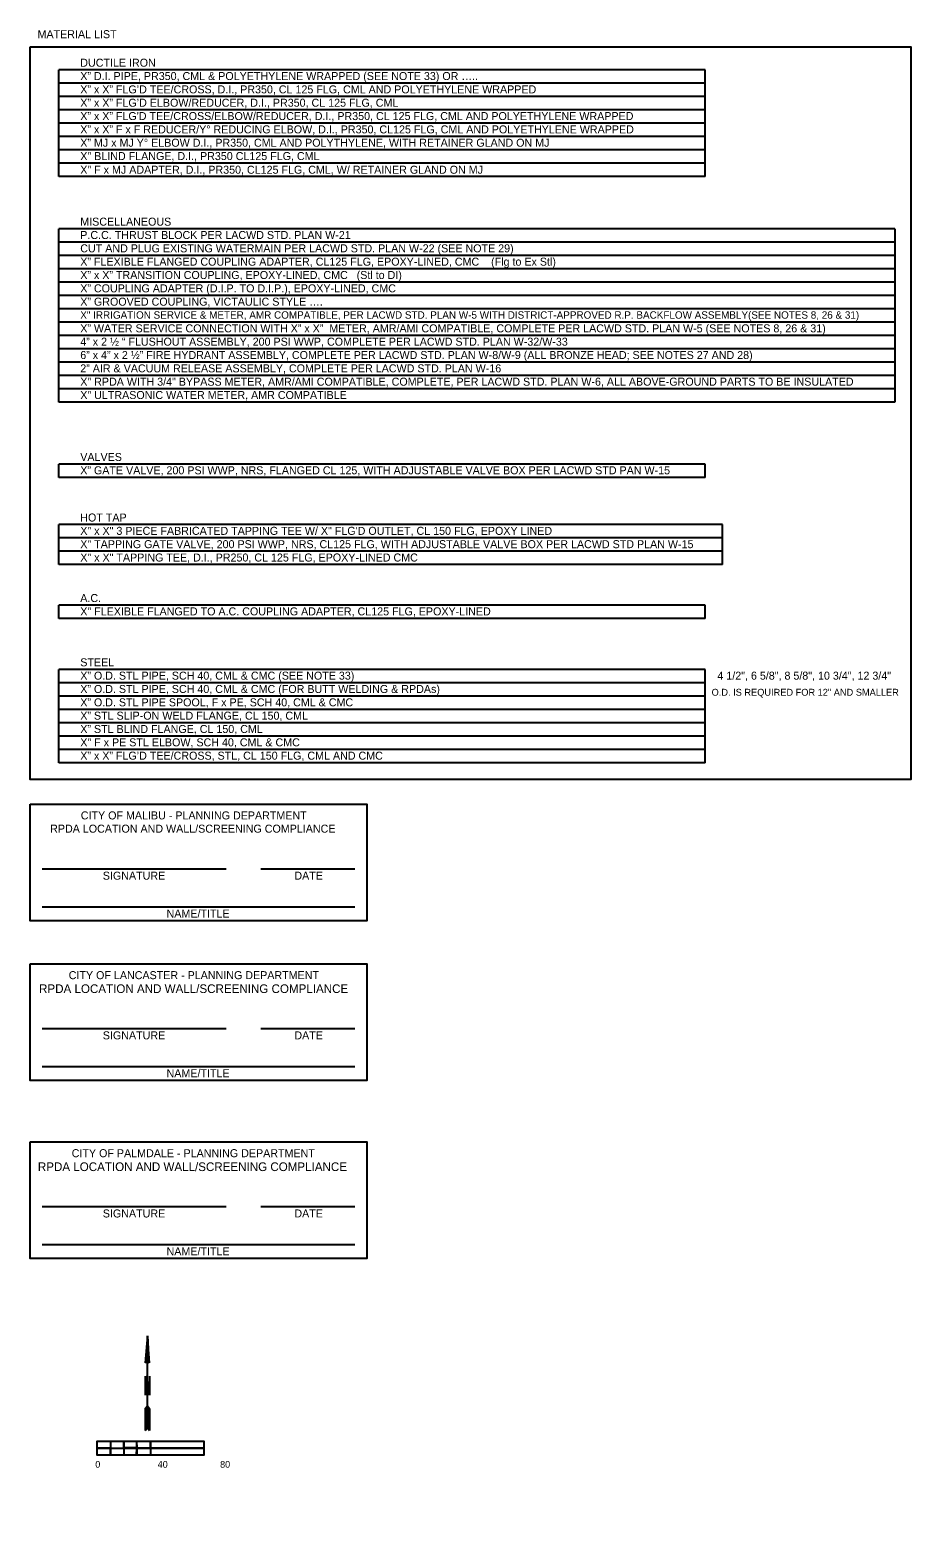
# Model space of a CAD drawing. Extents: x 837 to 1117, y 1316 to 1424.
# Drawn here: x 880.54 to 893.75, y 1401.27 to 1423.81 of the extents above; entities that cross this region are included whole.
import ezdxf

# ---------------------------------------------------------------- set-up
doc = ezdxf.new("R2010")
doc.units = 0
for name, color, linetype in [('BASEMAP', 7, 'Continuous'), ('LLINES', 7, 'Continuous'), ('TEXT', 7, 'Continuous')]:
    doc.layers.add(name, color=color, linetype=linetype)

# ---------------------------------------------------------------- blocks, each defined once
blk = doc.blocks.new('_U0')
at = {"layer": 'LLINES'}
for p, q in [((0, 1378), (-79, 591)), ((0, 1378), (-64, 606)), ((0, 1378), (-49, 620)), ((0, 1378), (-35, 634)), ((0, 1378), (-22, 647)), ((0, 1378), (-9, 660)), ((79, 591), (0, 1378)), ((0, 1378), (4, 666)), ((0, 1378), (43, 626)), ((0, 1378), (57, 612)), ((0, 1378), (29, 640)), ((2, 1302), (16, 653)), ((-79, 591), (0, 669)), ((0, 39), (0, 669)), ((0, 669), (79, 591)), ((16, 654), (29, 642)), ((-79, 197), (79, -118)), ((-79, 197), (-79, -354)), ((-79, 189), (79, -126)), ((-79, 181), (79, -134)), ((-79, 173), (79, -142)), ((-79, 165), (79, -150)), ((-79, 157), (79, -157)), ((-79, 150), (79, -165)), ((-79, 142), (79, -173)), ((-79, 134), (79, -181)), ((-79, 126), (79, -189)), ((-79, 118), (79, -197)), ((-79, 110), (79, -205)), ((-79, 102), (79, -213)), ((-79, 94), (79, -220)), ((-79, 87), (79, -228)), ((-79, 79), (79, -236)), ((-79, 71), (79, -244)), ((-79, 63), (79, -252)), ((-79, 55), (79, -260)), ((-79, 47), (79, -268)), ((-79, 39), (79, -276)), ((-79, 31), (79, -283)), ((-79, 24), (79, -291)), ((-79, 16), (79, -299)), ((-79, 8), (79, -307)), ((79, 197), (79, -354)), ((-79, 0), (79, -315)), ((-79, -8), (79, -323)), ((-79, -16), (79, -331)), ((-79, -24), (79, -339)), ((-79, -31), (79, -346)), ((-79, -39), (79, -354)), ((-79, -39), (79, -354)), ((0, -669), (0, -197)), ((0, -669), (-79, -748)), ((0, -669), (-79, -748)), ((0, -669), (-79, -748)), ((-79, -748), (-79, -1378)), ((-79, -748), (-79, -1378)), ((-79, -748), (-79, -1378)), ((-71, -748), (-71, -740)), ((-71, -748), (-71, -1370)), ((-63, -748), (-63, -732)), ((-63, -748), (-63, -1362)), ((-55, -748), (-55, -724)), ((-55, -748), (-55, -1354)), ((-47, -748), (-47, -717)), ((-47, -748), (-47, -1346)), ((-39, -748), (-39, -709)), ((-39, -748), (-39, -1339)), ((-31, -748), (-31, -701)), ((-31, -748), (-31, -1331)), ((-24, -748), (-24, -693)), ((-24, -748), (-24, -1323)), ((-16, -748), (-16, -685)), ((-16, -748), (-16, -1315)), ((-8, -748), (-8, -677)), ((-8, -748), (-8, -1307)), ((-8, -748), (-8, -1307)), ((0, -748), (0, -631)), ((79, -748), (0, -669)), ((0, -748), (0, -1299)), ((8, -748), (8, -677)), ((8, -748), (8, -1307)), ((16, -748), (16, -685)), ((16, -748), (16, -1315)), ((24, -748), (24, -693)), ((24, -748), (24, -1323)), ((31, -748), (31, -701)), ((31, -748), (31, -1331)), ((39, -748), (39, -709)), ((39, -748), (39, -1339)), ((47, -748), (47, -717)), ((47, -748), (47, -1346)), ((55, -748), (55, -724)), ((55, -748), (55, -1354)), ((63, -748), (63, -732)), ((63, -748), (63, -1362)), ((71, -748), (71, -740)), ((71, -748), (71, -1370)), ((79, -1378), (79, -748)), ((79, -748), (79, -1378)), ((-79, -1378), (0, -1299)), ((0, -1299), (79, -1378))]:
    blk.add_line(p, q, dxfattribs=at)
blk = doc.blocks.new('_U8')
at = {"layer": 'LLINES'}
for p, q in [((-2.295, -1.877), (1.489, 2.511)), ((-0.692, 0.559), (-0.114, 0.074)), ((-1.185, -0.013), (-0.626, -0.481)), ((-2.111, -1.086), (-1.533, -1.571))]:
    blk.add_line(p, q, dxfattribs=at)
for points in [[(-2.584, -1.635), (1.2, 2.753), (1.778, 2.268), (-2.006, -2.12)], [(-0.692, 0.559), (1.2, 2.753), (1.489, 2.511), (-0.403, 0.317)], [(-0.915, -0.239), (-0.422, 0.333), (-0.114, 0.074), (-0.607, -0.498)], [(-1.822, -1.329), (-1.349, -0.78), (-1.06, -1.023), (-1.533, -1.571)], [(-1.638, -0.538), (-1.185, -0.013), (-0.903, -0.249), (-1.356, -0.774)], [(-1.822, -1.329), (-2.295, -1.877), (-2.584, -1.635), (-2.111, -1.086)]]:
    blk.add_lwpolyline(points, close=True, dxfattribs=at)
blk.add_lwpolyline([(-2.584, -1.635), (-1.638, -0.538), (-1.06, -1.023)], dxfattribs=at)
blk.add_text('0                       40                     80', height=0.36477, rotation=49.23155, dxfattribs=at).set_placement((-1.549, -2.642))
blk = doc.blocks.new('_U3')
at = {"layer": 'BASEMAP'}
for p, q in [((-2.343, 0.365), (0.416, 0.365)), ((0.936, 0.365), (2.343, 0.365)), ((-2.343, -0.203), (2.343, -0.203))]:
    blk.add_line(p, q, dxfattribs=at)
at = {"layer": 'TEXT'}
for s, p in [('SIGNATURE', (-1.435, 0.203)), ('DATE', (1.438, 0.203)), ('NAME/TITLE', (-0.479, -0.365))]:
    blk.add_text(s, height=0.12, dxfattribs=at).set_placement(p)
blk = doc.blocks.new('_U5')
at = {"layer": 'BASEMAP'}
for p, q in [((-2.343, 0.365), (0.416, 0.365)), ((0.936, 0.365), (2.343, 0.365)), ((-2.343, -0.203), (2.343, -0.203))]:
    blk.add_line(p, q, dxfattribs=at)
at = {"layer": 'TEXT'}
for s, p in [('SIGNATURE', (-1.435, 0.203)), ('DATE', (1.438, 0.203)), ('NAME/TITLE', (-0.479, -0.365))]:
    blk.add_text(s, height=0.12, dxfattribs=at).set_placement(p)
blk = doc.blocks.new('_U7')
at = {"layer": 'BASEMAP'}
for p, q in [((-2.343, 0.365), (0.416, 0.365)), ((0.936, 0.365), (2.343, 0.365)), ((-2.343, -0.203), (2.343, -0.203))]:
    blk.add_line(p, q, dxfattribs=at)
at = {"layer": 'TEXT'}
for s, p in [('SIGNATURE', (-1.435, 0.203)), ('DATE', (1.438, 0.203)), ('NAME/TITLE', (-0.479, -0.365))]:
    blk.add_text(s, height=0.12, dxfattribs=at).set_placement(p)

msp = doc.modelspace()

# ---------------------------------------------------------------- linework, layer by layer
at = {"layer": 'BASEMAP'}
for p, q in [((890.667, 1423.212), (880.972, 1423.212)), ((880.972, 1423.012), (880.972, 1423.212)), ((890.667, 1423.012), (890.667, 1423.212)), ((890.667, 1423.012), (880.972, 1423.012)), ((880.972, 1422.812), (880.972, 1423.012)), ((890.667, 1422.812), (890.667, 1423.012)), ((890.667, 1422.812), (880.972, 1422.812)), ((880.972, 1422.612), (880.972, 1422.812)), ((890.667, 1422.612), (890.667, 1422.812)), ((890.667, 1422.612), (880.972, 1422.612)), ((880.972, 1422.412), (880.972, 1422.612)), ((890.667, 1422.412), (890.667, 1422.612)), ((890.667, 1422.412), (880.972, 1422.412)), ((880.972, 1422.212), (880.972, 1422.412)), ((890.667, 1422.212), (890.667, 1422.412)), ((890.667, 1422.212), (880.972, 1422.212)), ((880.972, 1422.012), (880.972, 1422.212)), ((890.667, 1422.012), (890.667, 1422.212)), ((890.667, 1422.012), (880.972, 1422.012)), ((880.972, 1421.812), (880.972, 1422.012)), ((890.667, 1421.812), (890.667, 1422.012)), ((890.667, 1421.812), (880.972, 1421.812)), ((880.972, 1421.612), (880.972, 1421.812)), ((890.667, 1421.612), (890.667, 1421.812)), ((890.667, 1421.612), (880.972, 1421.612)), ((893.508, 1420.828), (880.972, 1420.828)), ((880.972, 1420.628), (880.972, 1420.828)), ((893.508, 1420.828), (893.508, 1418.228)), ((893.508, 1420.628), (880.972, 1420.628)), ((880.972, 1420.428), (880.972, 1420.628)), ((893.508, 1420.428), (880.972, 1420.428)), ((880.972, 1420.228), (880.972, 1420.428)), ((893.508, 1420.228), (880.972, 1420.228)), ((880.972, 1420.028), (880.972, 1420.228)), ((893.508, 1420.028), (880.972, 1420.028)), ((880.972, 1419.828), (880.972, 1420.028)), ((893.508, 1419.828), (880.972, 1419.828)), ((880.972, 1419.628), (880.972, 1419.828)), ((893.508, 1419.628), (880.972, 1419.628)), ((880.972, 1419.428), (880.972, 1419.628)), ((893.508, 1419.428), (880.972, 1419.428)), ((880.972, 1419.228), (880.972, 1419.428)), ((893.508, 1419.228), (880.972, 1419.228)), ((880.972, 1419.028), (880.972, 1419.228)), ((893.508, 1419.028), (880.972, 1419.028)), ((880.972, 1418.828), (880.972, 1419.028)), ((893.508, 1418.828), (880.972, 1418.828)), ((880.972, 1418.628), (880.972, 1418.828)), ((893.508, 1418.628), (880.972, 1418.628)), ((880.972, 1418.428), (880.972, 1418.628)), ((893.508, 1418.428), (880.972, 1418.428)), ((880.972, 1418.228), (880.972, 1418.428)), ((893.508, 1418.228), (880.972, 1418.228)), ((890.667, 1417.299), (880.972, 1417.299)), ((880.972, 1417.099), (880.972, 1417.299)), ((890.667, 1417.099), (890.667, 1417.299)), ((890.667, 1417.099), (880.972, 1417.099)), ((890.923, 1416.391), (880.972, 1416.391)), ((880.972, 1416.191), (880.972, 1416.391)), ((890.923, 1416.191), (890.923, 1416.391)), ((890.923, 1416.191), (880.972, 1416.191)), ((880.972, 1415.991), (880.972, 1416.191)), ((890.923, 1415.991), (890.923, 1416.191)), ((890.923, 1415.991), (880.972, 1415.991)), ((880.972, 1415.791), (880.972, 1415.991)), ((890.923, 1415.791), (880.972, 1415.791)), ((890.923, 1415.791), (890.923, 1415.991)), ((890.667, 1415.183), (880.972, 1415.183)), ((880.972, 1414.983), (880.972, 1415.183)), ((890.667, 1414.983), (890.667, 1415.183)), ((890.667, 1414.983), (880.972, 1414.983)), ((890.667, 1414.219), (880.972, 1414.219)), ((880.972, 1414.019), (880.972, 1414.219)), ((890.667, 1414.019), (890.667, 1414.219)), ((890.667, 1414.019), (880.972, 1414.019)), ((880.972, 1413.819), (880.972, 1414.019)), ((890.667, 1413.819), (890.667, 1414.019)), ((890.667, 1413.819), (880.972, 1413.819)), ((880.972, 1413.619), (880.972, 1413.819)), ((890.667, 1413.619), (890.667, 1413.819)), ((890.667, 1413.619), (880.972, 1413.619)), ((880.972, 1413.419), (880.972, 1413.619)), ((890.667, 1413.419), (890.667, 1413.619)), ((890.667, 1413.419), (880.972, 1413.419)), ((880.972, 1413.219), (880.972, 1413.419)), ((890.667, 1413.219), (890.667, 1413.419)), ((890.667, 1413.219), (880.972, 1413.219)), ((880.972, 1413.019), (880.972, 1413.219)), ((890.667, 1413.019), (890.667, 1413.219)), ((890.667, 1413.019), (880.972, 1413.019)), ((880.972, 1412.819), (880.972, 1413.019)), ((890.667, 1412.819), (890.667, 1413.019)), ((890.667, 1412.819), (880.972, 1412.819))]:
    msp.add_line(p, q, dxfattribs=at)
for points in [[(880.54, 1423.555), (893.752, 1423.555), (893.752, 1412.567), (880.54, 1412.567)], [(880.54, 1412.199), (885.593, 1412.199), (885.593, 1410.448), (880.54, 1410.448)], [(880.54, 1409.803), (885.593, 1409.803), (885.593, 1408.052), (880.54, 1408.052)], [(880.54, 1407.133), (885.593, 1407.133), (885.593, 1405.382), (880.54, 1405.382)]]:
    msp.add_lwpolyline(points, close=True, dxfattribs=at)

# ---------------------------------------------------------------- block references
for name, p in [('_U3', (883.066, 1410.862)), ('_U5', (883.066, 1408.467)), ('_U7', (883.066, 1405.796))]:
    msp.add_blockref(name, p, dxfattribs=at)
at = {"layer": 'LLINES', "xscale": 0.00041148, "yscale": 0.00051435}
msp.add_blockref('_U0', (882.3, 1403.515), dxfattribs=at)
at = {"layer": 'LLINES', "xscale": 0.2741438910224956, "yscale": 0.27786097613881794, "rotation": -49.61278499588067}
msp.add_blockref('_U8', (882.352, 1402.398), dxfattribs=at)

# ---------------------------------------------------------------- texts
at = {"layer": 'LLINES'}
for s, height, p in [('MATERIAL LIST', 0.12, (880.652, 1423.686)), ('DUCTILE IRON', 0.12, (881.293, 1423.258)), ('X” D.I. PIPE, PR350, CML & POLYETHYLENE WRAPPED (SEE NOTE 33) OR …..', 0.12, (881.293, 1423.058)), ('X” x X” FLG’D TEE/CROSS, D.I., PR350, CL 125 FLG, CML AND POLYETHYLENE WRAPPED', 0.12, (881.293, 1422.858)), ('X” x X” FLG’D ELBOW/REDUCER, D.I., PR350, CL 125 FLG, CML', 0.12, (881.293, 1422.658)), ("X” x X” FLG'D TEE/CROSS/ELBOW/REDUCER, D.I., PR350, CL 125 FLG, CML AND POLYETHYLENE WRAPPED", 0.12, (881.293, 1422.458)), ('X” x X” F x F REDUCER/Y° REDUCING ELBOW, D.I., PR350, CL125 FLG, CML AND POLYETHYLENE WRAPPED', 0.12, (881.293, 1422.258)), ('X” MJ x MJ Y° ELBOW D.I., PR350, CML AND POLYTHYLENE, WITH RETAINER GLAND ON MJ', 0.12, (881.293, 1422.058)), ('X" BLIND FLANGE, D.I., PR350 CL125 FLG, CML', 0.12, (881.293, 1421.858)), ('X" F x MJ ADAPTER, D.I., PR350, CL125 FLG, CML, W/ RETAINER GLAND ON MJ', 0.12, (881.293, 1421.653)), ('MISCELLANEOUS', 0.12, (881.293, 1420.874)), ('P.C.C. THRUST BLOCK PER LACWD STD. PLAN W-21', 0.12, (881.293, 1420.674)), ('CUT AND PLUG EXISTING WATERMAIN PER LACWD STD. PLAN W-22 (SEE NOTE 29)', 0.12, (881.293, 1420.474)), ('X” FLEXIBLE FLANGED COUPLING ADAPTER, CL125 FLG, EPOXY-LINED, CMC    (Flg to Ex Stl)', 0.12, (881.293, 1420.274)), ('X” x X” TRANSITION COUPLING, EPOXY-LINED, CMC   (Stl to DI)', 0.12, (881.293, 1420.074)), ('X” COUPLING ADAPTER (D.I.P. TO D.I.P.), EPOXY-LINED, CMC', 0.12, (881.293, 1419.874)), ('X” GROOVED COUPLING, VICTAULIC STYLE ….', 0.12, (881.293, 1419.674)), ('X" IRRIGATION SERVICE & METER, AMR COMPATIBLE, PER LACWD STD. PLAN W-5 WITH DISTRICT-APPROVED R.P. BACKFLOW ASSEMBLY(SEE NOTES 8, 26 & 31)', 0.111002, (881.293, 1419.479)), ('X” WATER SERVICE CONNECTION WITH X” x X”  METER, AMR/AMI COMPATIBLE, COMPLETE PER LACWD STD. PLAN W-5 (SEE NOTES 8, 26 & 31)', 0.12, (881.293, 1419.274)), ('4” x 2 ½ “ FLUSHOUT ASSEMBLY, 200 PSI WWP, COMPLETE PER LACWD STD. PLAN W-32/W-33', 0.12, (881.293, 1419.074)), ('6” x 4” x 2 ½” FIRE HYDRANT ASSEMBLY, COMPLETE PER LACWD STD. PLAN W-8/W-9 (ALL BRONZE HEAD; SEE NOTES 27 AND 28)', 0.12, (881.293, 1418.874)), ('2” AIR & VACUUM RELEASE ASSEMBLY, COMPLETE PER LACWD STD. PLAN W-16', 0.12, (881.293, 1418.674)), ('X" RPDA WITH 3/4" BYPASS METER, AMR/AMI COMPATIBLE, COMPLETE, PER LACWD STD. PLAN W-6, ALL ABOVE-GROUND PARTS TO BE INSULATED', 0.12, (881.293, 1418.474)), ('X" ULTRASONIC WATER METER, AMR COMPATIBLE ', 0.12, (881.293, 1418.274)), ('VALVES', 0.12, (881.293, 1417.345)), ('X” GATE VALVE, 200 PSI WWP, NRS, FLANGED CL 125, WITH ADJUSTABLE VALVE BOX PER LACWD STD PAN W-15', 0.12, (881.293, 1417.145)), ('HOT TAP', 0.12, (881.293, 1416.437)), ('X" x X" 3 PIECE FABRICATED TAPPING TEE W/ X" FLG\'D OUTLET, CL 150 FLG, EPOXY LINED', 0.12, (881.293, 1416.237)), ('X" TAPPING GATE VALVE, 200 PSI WWP, NRS, CL125 FLG, WITH ADJUSTABLE VALVE BOX PER LACWD STD PLAN W-15', 0.12, (881.293, 1416.037)), ('X" x X" TAPPING TEE, D.I., PR250, CL 125 FLG, EPOXY-LINED CMC', 0.12, (881.293, 1415.837)), ('A.C.', 0.12, (881.293, 1415.229)), ('X" FLEXIBLE FLANGED TO A.C. COUPLING ADAPTER, CL125 FLG, EPOXY-LINED', 0.12, (881.293, 1415.029)), ('X” O.D. STL PIPE, SCH 40, CML & CMC (SEE NOTE 33)', 0.12, (881.293, 1414.065)), ('STEEL', 0.12, (881.293, 1414.265)), ('4 1/2", 6 5/8", 8 5/8", 10 3/4", 12 3/4"', 0.12, (890.849, 1414.065)), ('X” O.D. STL PIPE, SCH 40, CML & CMC (FOR BUTT WELDING & RPDAs)', 0.12, (881.293, 1413.865)), ('X” O.D. STL PIPE SPOOL, F x PE, SCH 40, CML & CMC', 0.12, (881.293, 1413.665)), ('O.D. IS REQUIRED FOR 12" AND SMALLER', 0.10344, (890.762, 1413.824)), ('X” STL SLIP-ON WELD FLANGE, CL 150, CML', 0.12, (881.293, 1413.465)), ('X” STL BLIND FLANGE, CL 150, CML', 0.12, (881.293, 1413.265)), ('X" F x PE STL ELBOW, SCH 40, CML & CMC', 0.12, (881.293, 1413.065)), ('X” x X” FLG’D TEE/CROSS, STL, CL 150 FLG, CML AND CMC', 0.12, (881.293, 1412.865))]:
    msp.add_text(s, height=height, dxfattribs=at).set_placement(p)
at = {"layer": 'TEXT'}
for s, height, p in [('CITY OF MALIBU - PLANNING DEPARTMENT', 0.12, (881.301, 1411.969)), ('RPDA LOCATION AND WALL/SCREENING COMPLIANCE', 0.12, (880.841, 1411.77)), ('CITY OF LANCASTER - PLANNING DEPARTMENT', 0.12, (881.12, 1409.573)), ('RPDA LOCATION AND WALL/SCREENING COMPLIANCE', 0.13, (880.675, 1409.365)), ('CITY OF PALMDALE - PLANNING DEPARTMENT', 0.12, (881.165, 1406.903)), ('RPDA LOCATION AND WALL/SCREENING COMPLIANCE', 0.13, (880.657, 1406.695))]:
    msp.add_text(s, height=height, dxfattribs=at).set_placement(p)

doc.saveas('drawing.dxf')
